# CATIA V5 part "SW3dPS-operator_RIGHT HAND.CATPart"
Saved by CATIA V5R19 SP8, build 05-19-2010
Part number: SW3dPS-operator_RIGHT HAND
Revision: ANY
Definition: SW3dPS-operator_RIGHT HAND
Source: Unknown
Bounding box of the stored display mesh (mm): x -69.85 to 185.216, y -77.34 to 31.75, z -55.245 to 42.545
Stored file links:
  G:\EU_thinkMotion\CFAO_2010\MMS_groupe1\MMS_groupe1\OK\rragonneau\rragonneau\SW3dPS-operator_RIGHT HAND.CATPart
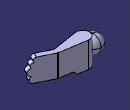
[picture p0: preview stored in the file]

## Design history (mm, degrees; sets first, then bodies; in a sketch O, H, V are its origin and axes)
Body1 "NONE" (main body)
  Solid1 "Manifold Solid #11713": solid without history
